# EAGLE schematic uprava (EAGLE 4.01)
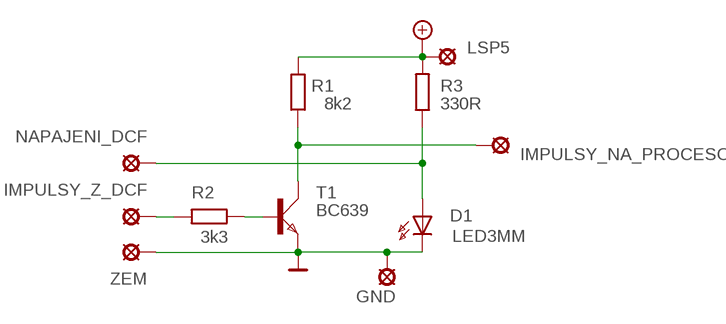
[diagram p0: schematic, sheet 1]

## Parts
D1  LED3MM  [LED3MM]
GND  LSP10  [LSP10]
IMPULSY_NA_PROCESOR  LSP10  [LSP10]
IMPULSY_Z_DCF  LSP10  [LSP10]
LSP5  LSP10  [LSP10]
NAPAJENI_DCF  LSP10  [LSP10]
R1  8k2  RR  [RR]
R2  3k3  RR  [RR]
R3  330R  RR  [RR]
T1  BC639  [SOT54D]
ZEM  LSP10  [LSP10]

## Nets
0V: D1.K(C) GND.MP T1.E ZEM.MP
+5V: LSP5.MP R1.2 R3.1
N$1: IMPULSY_NA_PROCESOR.MP R1.1 T1.C
N$2: D1.A NAPAJENI_DCF.MP R3.2
N$5: R2.2 T1.B
N$6: IMPULSY_Z_DCF.MP R2.1

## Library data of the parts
D1 = led:LED3MM: LED
GND IMPULSY_NA_PROCESOR IMPULSY_Z_DCF LSP5 NAPAJENI_DCF ZEM = solpad:LSP10: SOLDER PAD
R1-R3 = GM99:RR
T1 = transistor-small-signal:BC639: NPN TRANSISTOR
